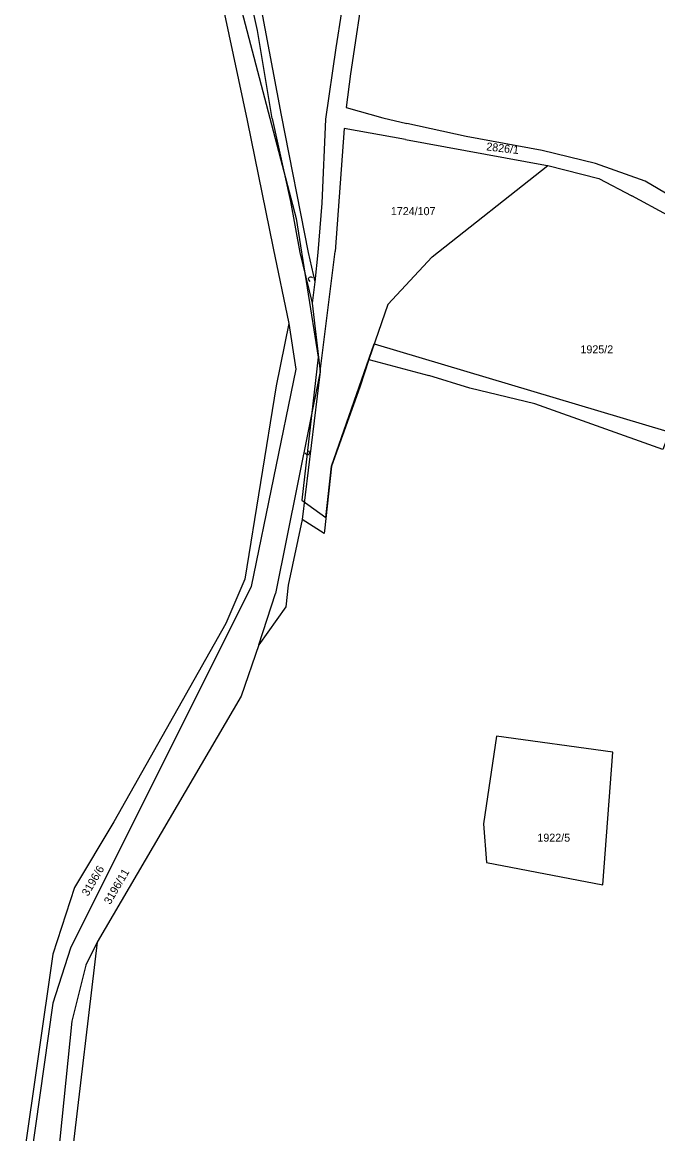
# Model space of a CAD drawing. Extents: x -581999 to -572728, y -1219553 to -1212032.
# Drawn here: x -578510.6 to -578351.7, y -1216348.4 to -1216070.7 of the extents above; entities that cross this region are included whole.
import ezdxf

# ---------------------------------------------------------------- set-up
doc = ezdxf.new("R2010")
doc.units = 0
for name, color, linetype in [('Vrstva 1', 7, 'Continuous'), ('Vrstva 2', 7, 'Continuous'), ('Vrstva 6', 7, 'Continuous'), ('Vrstva 63', 7, 'Continuous')]:
    doc.layers.add(name, color=color, linetype=linetype)

msp = doc.modelspace()

# ---------------------------------------------------------------- linework, layer by layer
at = {"layer": 'Vrstva 1'}
for p, q in [((-578451.83, -1216072.7), (-578455.453, -1216056.08)), ((-578448.125, -1216094.748), (-578451.83, -1216072.7)), ((-578445.867, -1216093.905), (-578439.091, -1216128.16)), ((-578439.091, -1216128.16), (-578437.464, -1216135.501)), ((-578436.151, -1216157.911), (-578432.372, -1216127.924)), ((-578438.104, -1216140.888), (-578436.151, -1216157.911)), ((-578443.953, -1216145.942), (-578442.196, -1216157.314)), ((-578442.196, -1216157.314), (-578453.332, -1216211.628)), ((-578436.151, -1216157.911), (-578447.287, -1216213.419)), ((-578436.151, -1216157.911), (-578440.605, -1216194.916)), ((-578447.094, -1216161.488), (-578454.923, -1216209.838)), ((-578440.605, -1216194.916), (-578444.105, -1216211.33)), ((-578453.332, -1216211.628), (-578498.511, -1216302.053)), ((-578454.923, -1216209.838), (-578459.695, -1216220.88)), ((-578444.105, -1216211.33), (-578444.742, -1216216.702)), ((-578451.423, -1216226.252), (-578447.287, -1216213.419)), ((-578444.742, -1216216.702), (-578451.423, -1216226.252)), ((-578459.695, -1216220.88), (-578487.694, -1216270.419)), ((-578451.423, -1216226.252), (-578455.877, -1216239.084)), ((-578455.877, -1216239.084), (-578491.83, -1216300.561)), ((-578487.694, -1216270.419), (-578497.557, -1216286.833)), ((-578497.557, -1216286.833), (-578502.965, -1216303.545)), ((-578491.83, -1216300.561), (-578498.829, -1216359.054)), ((-578491.83, -1216300.561), (-578494.693, -1216306.231)), ((-578502.965, -1216303.545), (-578510.601, -1216356.666)), ((-578498.511, -1216302.053), (-578502.965, -1216315.781)), ((-578494.693, -1216306.231), (-578498.193, -1216320.258)), ((-578502.965, -1216315.781), (-578509.329, -1216361.143)), ((-578498.193, -1216320.258), (-578508.664, -1216422.165))]:
    msp.add_line(p, q, dxfattribs=at)
for points in [[(-578423.953, -1216022.261), (-578426.584, -1216040.546), (-578429.359, -1216059.01), (-578432.197, -1216077.046), (-578434.785, -1216094.886)], [(-578453.456, -1216056.034), (-578451.017, -1216066.447), (-578445.867, -1216093.905)], [(-578424.925, -1216059.633), (-578428.503, -1216083.533), (-578429.613, -1216091.929), (-578420.5, -1216094.532), (-578414.467, -1216095.958)], [(-578460.074, -1216068.613), (-578454.346, -1216095.173)], [(-578454.346, -1216095.173), (-578447.888, -1216127.106)], [(-578448.125, -1216094.748), (-578443.577, -1216115.445), (-578441.237, -1216128.223)], [(-578434.785, -1216094.886), (-578435.695, -1216115.886), (-578436.743, -1216128.228)], [(-578414.76, -1216099.923), (-578430.09, -1216097.251), (-578432.372, -1216127.924)], [(-578326.718, -1216125.807), (-578348.362, -1216114.208), (-578354.9, -1216110.4), (-578367.317, -1216105.978), (-578380.597, -1216102.705), (-578399.615, -1216099.233), (-578414.467, -1216095.958)], [(-578414.76, -1216099.923), (-578379.812, -1216106.352), (-578379.229, -1216106.414)], [(-578408.124, -1216129.316), (-578379.229, -1216106.414)], [(-578379.229, -1216106.414), (-578366.436, -1216109.721), (-578358.202, -1216114.006)], [(-578331.465, -1216128.501), (-578358.202, -1216114.006)], [(-578447.888, -1216127.106), (-578443.953, -1216145.942), (-578447.094, -1216161.488)], [(-578441.237, -1216128.223), (-578438.104, -1216140.888)], [(-578436.743, -1216128.228), (-578437.464, -1216135.501), (-578438.104, -1216140.888)], [(-578331.465, -1216128.501), (-578339.85, -1216149.839), (-578350.454, -1216177.45), (-578382.446, -1216166.028), (-578398.686, -1216162.087), (-578408.932, -1216158.93)], [(-578408.124, -1216129.316), (-578419.206, -1216141.215), (-578423.948, -1216154.907)], [(-578423.948, -1216154.907), (-578426.227, -1216161.814), (-578433.301, -1216181.553), (-578435.026, -1216197.71), (-578435.088, -1216198.388), (-578440.605, -1216194.916)], [(-578423.948, -1216154.907), (-578408.932, -1216158.93)], [(-578392.075, -1216249.018), (-578395.298, -1216270.967), (-578394.536, -1216280.635), (-578365.45, -1216286.166), (-578362.984, -1216253.021), (-578392.075, -1216249.018)]]:
    msp.add_lwpolyline(points, dxfattribs=at)
at = {"layer": 'Vrstva 6'}
for points in [[(-578438.661, -1216135.444), (-578439.218, -1216134.796), (-578438.737, -1216134.208), (-578438.337, -1216134.237), (-578438.157, -1216134.443), (-578438.066, -1216134.522)], [(-578439.977, -1216178.269), (-578439.401, -1216178.901), (-578438.759, -1216178.494), (-578438.74, -1216178.093), (-578438.922, -1216177.89), (-578438.989, -1216177.79)]]:
    msp.add_open_spline(points, degree=3, dxfattribs=at)
at = {"layer": 'Vrstva 63'}
for p, q in [((-578462.74, -1216041.281), (-578442.106, -1216119.73)), ((-578442.106, -1216119.73), (-578436.604, -1216154.334)), ((-578433.301, -1216181.553), (-578422.623, -1216151.047)), ((-578422.623, -1216151.047), (-578349.238, -1216172.932)), ((-578436.604, -1216154.334), (-578440.727, -1216190.039)), ((-578434.694, -1216194.406), (-578433.301, -1216181.553)), ((-578440.727, -1216190.039), (-578434.694, -1216194.406))]:
    msp.add_line(p, q, dxfattribs=at)

# ---------------------------------------------------------------- texts
at = {"layer": 'Vrstva 2'}
for s, rotation, p in [('2826/1', 353.36311, (-578394.681, -1216102.661)), ('3196/6', 59.60371, (-578494.144, -1216289.191)), ('3196/11', 59.60371, (-578488.61, -1216291.264))]:
    msp.add_text(s, height=2, rotation=rotation, dxfattribs=at).set_placement(p)
for s, p in [('1724/107', (-578418.455, -1216118.86)), ('1925/2', (-578371.063, -1216153.392)), ('1922/5', (-578381.827, -1216275.416))]:
    msp.add_text(s, height=2, dxfattribs=at).set_placement(p)

doc.saveas('drawing.dxf')
